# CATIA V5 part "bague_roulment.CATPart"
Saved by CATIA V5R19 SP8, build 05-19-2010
Part number: bague_roulement
Revision: ANY
Definition: UNKNOWN
Nomenclature: bague_roulment
Source: Unknown
Bounding box of the stored display mesh (mm): x -2 to 2, y -2 to 0, z 0 to 8
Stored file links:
  D:\Documents\1_Travail\2- 2I2D\1 - Cours et TD\2- TD\3-TD Assemblage\Pompe AirMan\bague_roulment.CATPart
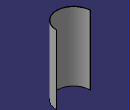
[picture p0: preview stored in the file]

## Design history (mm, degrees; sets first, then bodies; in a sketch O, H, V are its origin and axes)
Body1 "Extrusion1" (main body)
  Solid1: solid without history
